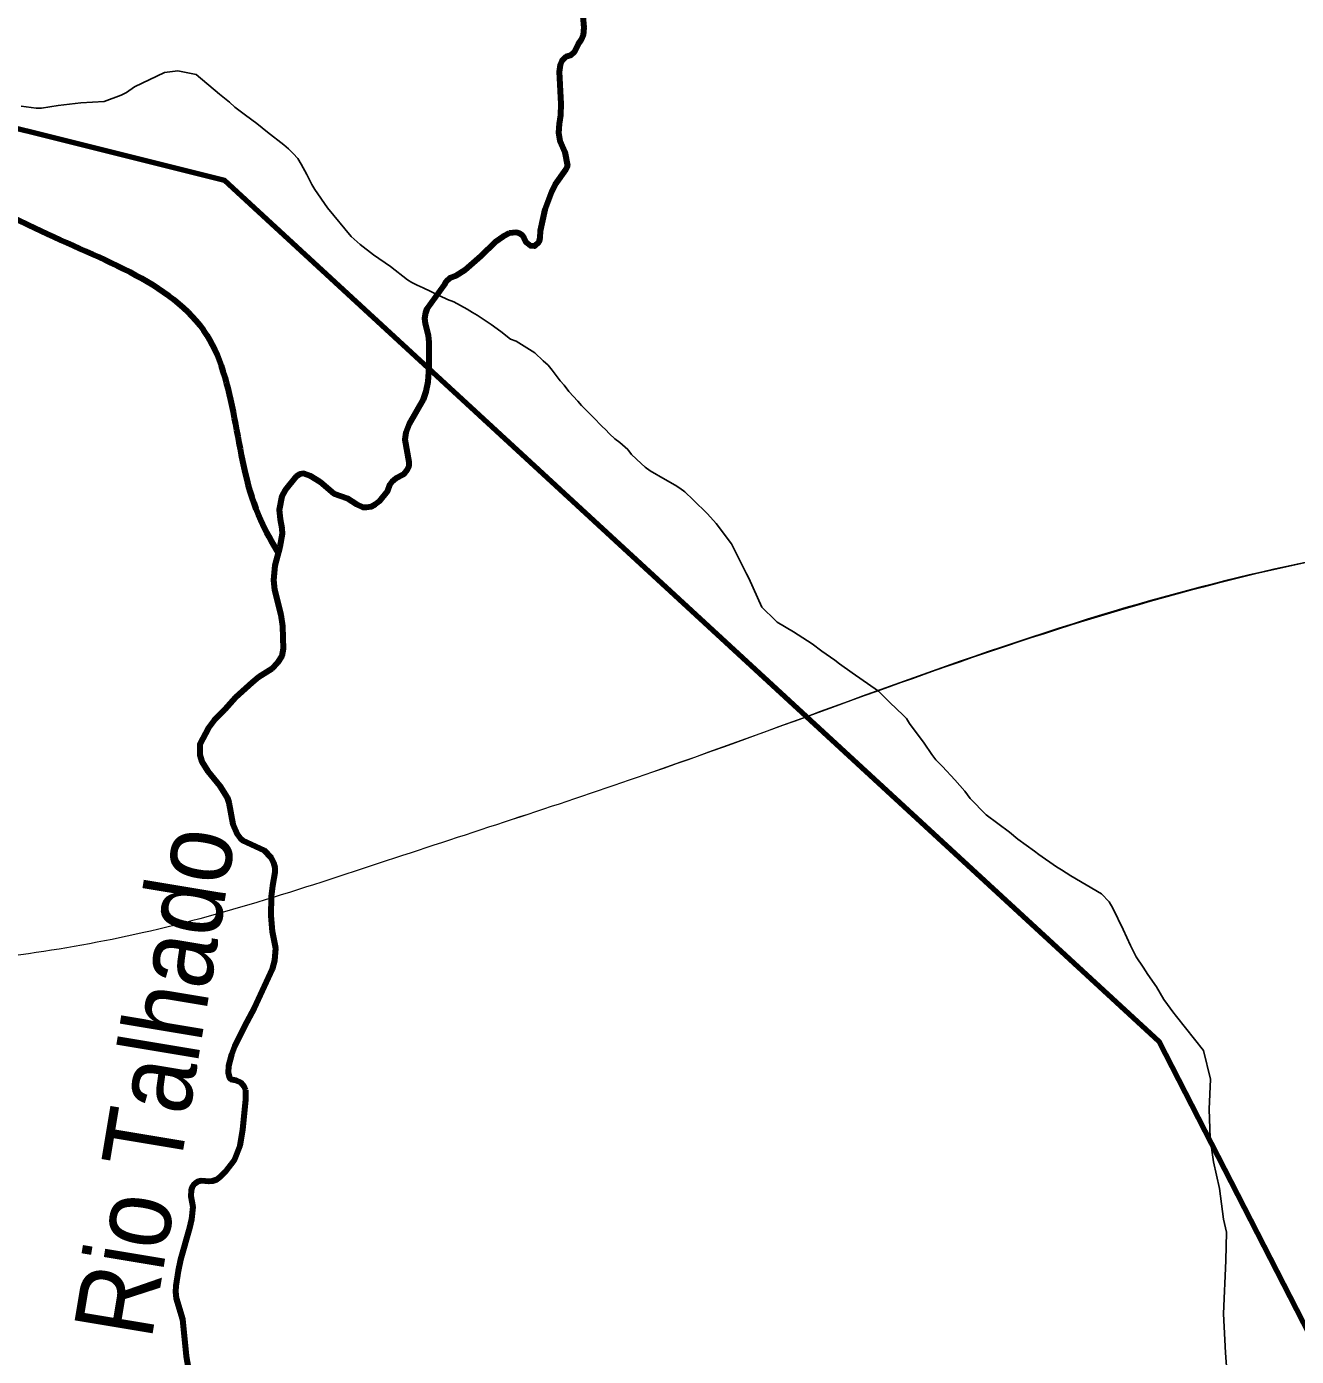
# Model space of a CAD drawing. Extents: x 553962 to 842807, y 8883888 to 9032388.
# Drawn here: x 619995 to 628026, y 8951515 to 8959925 of the extents above; entities that cross this region are included whole.
import ezdxf
from ezdxf.enums import TextEntityAlignment as Align

# ---------------------------------------------------------------- set-up
doc = ezdxf.new("R2010")
doc.units = 0
doc.header["$LTSCALE"] = 200
for name, color, linetype, lineweight in [('12', 7, 'Continuous', 25), ('24', 7, 'Continuous', 25), ('28', 7, 'Continuous', 40), ('57', 7, 'Continuous', 13), ('9', 7, 'Continuous', 90)]:
    doc.layers.add(name, color=color, linetype=linetype, lineweight=lineweight)
doc.layers.add('49', color=7, linetype='Continuous')

msp = doc.modelspace()

# ---------------------------------------------------------------- linework, layer by layer
at = {"layer": '12'}
for points in [[(619960.1, 8959421.4), (620056, 8959410.5), (620088, 8959410.6), (620193.3, 8959426.8), (620302, 8959438.9), (620338.3, 8959444), (620485.1, 8959452.2), (620592.3, 8959491.5), (620626.6, 8959508.6), (620677.1, 8959543.7), (620866.8, 8959636.1), (620950.1, 8959645.3), (621067.6, 8959622.4), (621213.8, 8959498.5), (621277.5, 8959446.5), (621310.7, 8959416.5), (621378.9, 8959364.5), (621451.2, 8959312.6), (621517.4, 8959257.6), (621620.6, 8959177.6), (621652, 8959151.6), (621681.1, 8959122.6), (621709.4, 8959090.6), (621730.8, 8959055.6), (621766, 8958989.6), (621797.6, 8958926.5), (621816.7, 8958894.5), (621897.9, 8958779.4), (622047.1, 8958598.4), (622104.4, 8958547.4), (622189, 8958482.4), (622295.2, 8958408.5), (622402.8, 8958323.5), (622432, 8958306.5), (622464.2, 8958290.6), (622503.3, 8958272.6), (622656.9, 8958198.7), (622695.9, 8958184.8), (622781.7, 8958137.8), (622814.5, 8958116.8), (622845, 8958100.9), (622933, 8958040.9), (622994, 8957997), (623055.6, 8957949), (623090.1, 8957935), (623208.6, 8957861.1), (623261.3, 8957811.1), (623293.1, 8957783.1), (623319, 8957753.1), (623370.1, 8957684.1), (623394.1, 8957657.1), (623423, 8957618), (623480.8, 8957556), (623503.5, 8957528), (623577.3, 8957455), (623634.3, 8957397), (623656.2, 8957377), (623681.5, 8957349), (623715.2, 8957318), (623746.4, 8957294), (623796.4, 8957250.1), (623820, 8957220), (623881.1, 8957162.1), (623907.7, 8957139.1), (623938.3, 8957116.1), (624032.6, 8957060.1), (624097.3, 8957025.2), (624126.4, 8957005.2), (624156.6, 8956982.2), (624209.6, 8956933.2), (624300.1, 8956843.2), (624356.6, 8956783.2), (624452.3, 8956653.2), (624547.5, 8956464), (624563.3, 8956437), (624643.8, 8956253.8), (624732.1, 8956169.8), (624741.4, 8956157.8), (624844.8, 8956096.9), (624963, 8956021), (625024.6, 8955976), (625106.9, 8955919.1), (625134.8, 8955896.1), (625215.8, 8955838.1), (625381.6, 8955722.2), (625453.3, 8955650.2), (625539.4, 8955570.2), (625559, 8955549.2), (625578.1, 8955517.2), (625672.3, 8955394.1), (625719.6, 8955321.1), (625744.1, 8955288.1), (625787.2, 8955246.1), (625865, 8955162.1), (625928.3, 8955090.1), (625962.8, 8955044), (626062.5, 8954941)], [(626062.5, 8954941), (626210.1, 8954830.1), (626263.6, 8954786.1), (626369.3, 8954710.2), (626395.7, 8954688.2), (626508.6, 8954610.2), (626539.2, 8954592.2), (626598.2, 8954554.3), (626792.1, 8954439.4), (626840.8, 8954390.4), (626864.8, 8954350.4), (626929.5, 8954214.3), (626976, 8954113.2), (627012.7, 8954042.1), (627056.3, 8953977.1), (627085.1, 8953931.1), (627140.4, 8953852), (627187.4, 8953773), (627209.8, 8953740), (627243.8, 8953694), (627268.1, 8953665), (627437.5, 8953449.9)], [(627437.5, 8953449.9), (627481.8, 8953267.7), (627474.2, 8953079.4), (627481, 8952894.1), (627502, 8952745.9), (627539.5, 8952577.7), (627565.1, 8952382.4), (627583.5, 8952301.3), (627578.9, 8952122), (627564.2, 8951783.5), (627578, 8951538.1), (627594.5, 8951309.8), (627615.6, 8951152.6), (627641.3, 8950944.3), (627690, 8950694), (627726.6, 8950540.8), (627780.8, 8950380.6), (627876.2, 8950172.5), (627886.3, 8950067.3), (627860.6, 8949911), (627825.7, 8949779.8), (627813.3, 8949686.6)]]:
    msp.add_lwpolyline(points, dxfattribs=at)
at = {"layer": '24'}
for points in [[(623511.8, 8959991.9), (623518.8, 8959918.8), (623515.2, 8959871.7), (623503, 8959841.6), (623483.8, 8959814.6), (623458.3, 8959764.4), (623435.3, 8959743.4), (623405.8, 8959733.3), (623380.1, 8959708.2), (623370, 8959684.2), (623363, 8959639.1), (623374, 8959437.8), (623371.3, 8959365.7), (623362.7, 8959309.6), (623359.5, 8959254.5), (623367, 8959203.4), (623399.7, 8959131.4), (623414.8, 8959045.2), (623404.2, 8959022.2), (623338.3, 8958926.9), (623315, 8958880.8), (623272.9, 8958769.6), (623243.1, 8958633.3), (623241.6, 8958590.3), (623234, 8958561.2), (623207.1, 8958537.1), (623180.9, 8958538.1), (623154, 8958559.1), (623142.4, 8958588.1), (623129.2, 8958606.1), (623114.3, 8958616.1), (623091.3, 8958624.1), (623048.1, 8958618)], [(623048.1, 8958618), (623008.6, 8958598.9), (622961, 8958563.8), (622867, 8958474.5), (622765.3, 8958385.2), (622710.3, 8958350.1), (622672.6, 8958336), (622645.8, 8958310.9), (622635.8, 8958292.8), (622526.4, 8958139.4), (622516.5, 8958114.4), (622511.7, 8958078.3), (622515.3, 8958048.3), (622533.3, 8957971.2), (622537.7, 8957930.1), (622539.2, 8957771.9), (622532.6, 8957678.7), (622519.6, 8957617.6), (622503, 8957566.5), (622414.7, 8957413.1), (622392.8, 8957358), (622387.2, 8957313.9), (622413.1, 8957173.7), (622412, 8957144.7), (622401.3, 8957121.6), (622379.3, 8957091.6), (622329.5, 8957067.4), (622303.6, 8957046.4), (622292.3, 8957028.3), (622277.2, 8956988.2), (622224.7, 8956922.1), (622199.4, 8956902), (622173.6, 8956888.9), (622144.5, 8956882.9), (622124.1, 8956884.8), (622082.2, 8956903.8), (622023.4, 8956940.8)], [(622023.4, 8956940.8), (621940, 8956970.7), (621852.9, 8957044.7), (621852.9, 8957044.7), (621788.3, 8957084.6), (621747.1, 8957098.6), (621722, 8957094.5), (621699.9, 8957079.5), (621630.5, 8956993.2), (621609.1, 8956955.1), (621593, 8956869), (621597.7, 8956809.9), (621609.5, 8956752.8), (621610.3, 8956716.8), (621596.7, 8956635.6), (621564.2, 8956517.4), (621555.7, 8956425.2), (621563.4, 8956363.1), (621602.1, 8956205), (621612.3, 8956132.8), (621617.2, 8955989.6), (621609.4, 8955942.6), (621581.9, 8955900.4), (621546.5, 8955864.3), (621462.3, 8955810.1), (621421.6, 8955778), (621315.5, 8955681.7), (621248.5, 8955606.5), (621180.3, 8955539.2), (621144.2, 8955490.1), (621090.8, 8955387.9), (621089.6, 8955318.8), (621102.6, 8955276.7), (621141.2, 8955216.7), (621216.2, 8955123.7), (621263.9, 8955050.6), (621273.7, 8955018.6), (621298.4, 8954880.4), (621326.6, 8954818.3), (621344.8, 8954792.3), (621361.2, 8954778.3), (621494.9, 8954716.5), (621540.7, 8954668.5), (621556.5, 8954637.4), (621563.9, 8954607.4), (621564.5, 8954574.3), (621548.8, 8954491.2), (621540.9, 8954424.1), (621539.7, 8954301.9), (621548, 8954202.7), (621568.6, 8954096.6), (621562.7, 8954019.5), (621547, 8953964.4), (621433.8, 8953717.8), (621371.7, 8953602.5), (621309.6, 8953474.2), (621290.3, 8953424.1), (621271.3, 8953352), (621268.5, 8953307.9), (621278.3, 8953276.9), (621286.8, 8953268.9), (621318.5, 8953261.9), (621350.1, 8953247.9), (621369.2, 8953222.9), (621379.6, 8953197.9)], [(621379.6, 8953197.9), (621378.8, 8953137.8), (621359.7, 8952949.5), (621342.4, 8952846.3), (621307.8, 8952755.1), (621249.5, 8952681.9), (621219.1, 8952650.8), (621195, 8952631.7), (621171.1, 8952622.7), (621146.2, 8952620.6), (621100.1, 8952625.6), (621079.8, 8952621.5), (621057, 8952606.5), (621039.6, 8952581.4), (621035.3, 8952565.4), (621033.6, 8952527.3), (621045.1, 8952461.2), (621037.1, 8952383.1), (621025.7, 8952328), (620968.5, 8952127.6), (620952.3, 8952055.4), (620937.5, 8951961.3), (620936.1, 8951922.2), (620941.1, 8951883.2), (620980.3, 8951750), (621003, 8951516.7), (621017.4, 8951444.6)]]:
    msp.add_lwpolyline(points, dxfattribs=at)
at = {"layer": '28', "lineweight": 80}
msp.add_lwpolyline([(610031.8, 8962217.2), (616214.5, 8960212.5), (621246, 8958953.8), (627155.1, 8953509.2), (629934.5, 8948091.8)], dxfattribs=at)
at = {"layer": '57'}
for points in [[(646003, 8949251.6), (644721.9, 8950215.5), (643492.6, 8951234.6), (642099.6, 8952556.8), (640992.4, 8953664.6), (640171, 8954236.3), (637456.5, 8955772.9), (636135, 8956237.5), (634599.2, 8956630.6), (632599.1, 8956773.5), (629063.1, 8956702), (626348.7, 8956058.8), (623953.8, 8955209.7), (622371.6, 8954682.1), (620725.9, 8954192.9), (619183.7, 8953970.3), (617209.7, 8953965.7), (615658.4, 8954379), (614681.6, 8955057.1), (613704.6, 8955684.2), (612906.2, 8956374.2), (612068.3, 8956835.4), (609416.9, 8956401.3), (608625.2, 8956035.7), (607870.9, 8955517.4), (607396.1, 8954883.6), (607164, 8954388.6), (606950.6, 8954069.9)], [(646003, 8949251.6), (644721.9, 8950215.5), (643521.3, 8951208.7), (642428.2, 8952239.5), (641741.8, 8952914.9), (640407.4, 8954089.3), (638333.9, 8955336.1), (636237.3, 8956206.4), (633646.8, 8956732.8), (631365, 8956802.2), (629312, 8956729.1), (626793.2, 8956204.6), (623953.8, 8955209.7), (622371.6, 8954682.1), (620725.9, 8954192.9), (619183.7, 8953970.3), (617209.7, 8953965.7), (615658.4, 8954379), (614681.6, 8955057.1), (613704.6, 8955684.2), (612906.2, 8956374.2), (612068.3, 8956835.4), (609416.9, 8956401.3), (608625.2, 8956035.7), (607870.9, 8955517.4), (607396.1, 8954883.6), (607164, 8954388.6), (606950.6, 8954069.9)]]:
    msp.add_spline(points, degree=3, dxfattribs=at)
at = {"layer": '9'}
for points in [[(623511.8, 8959991.9), (623518.8, 8959918.8), (623515.2, 8959871.7), (623503, 8959841.6), (623483.8, 8959814.6), (623458.3, 8959764.4), (623435.3, 8959743.4), (623405.8, 8959733.3), (623380.1, 8959708.2), (623370, 8959684.2), (623363, 8959639.1), (623374, 8959437.8), (623371.3, 8959365.7), (623362.7, 8959309.6), (623359.5, 8959254.5), (623367, 8959203.4), (623399.7, 8959131.4), (623414.8, 8959045.2), (623404.2, 8959022.2), (623338.3, 8958926.9), (623315, 8958880.8), (623272.9, 8958769.6), (623243.1, 8958633.3), (623241.6, 8958590.3), (623234, 8958561.2), (623207.1, 8958537.1), (623180.9, 8958538.1), (623154, 8958559.1), (623142.4, 8958588.1), (623129.2, 8958606.1), (623114.3, 8958616.1), (623091.3, 8958624.1), (623048.1, 8958618)], [(623048.1, 8958618), (623008.6, 8958598.9), (622961, 8958563.8), (622867, 8958474.5), (622765.3, 8958385.2), (622710.3, 8958350.1), (622672.6, 8958336), (622645.8, 8958310.9), (622635.8, 8958292.8), (622526.4, 8958139.4), (622516.5, 8958114.4), (622511.7, 8958078.3), (622515.3, 8958048.3), (622533.3, 8957971.2), (622537.7, 8957930.1), (622539.2, 8957771.9), (622532.6, 8957678.7), (622519.6, 8957617.6), (622503, 8957566.5), (622414.7, 8957413.1), (622392.8, 8957358), (622387.2, 8957313.9), (622413.1, 8957173.7), (622412, 8957144.7), (622401.3, 8957121.6), (622379.3, 8957091.6), (622329.5, 8957067.4), (622303.6, 8957046.4), (622292.3, 8957028.3), (622277.2, 8956988.2), (622224.7, 8956922.1), (622199.4, 8956902), (622173.6, 8956888.9), (622144.5, 8956882.9), (622124.1, 8956884.8), (622082.2, 8956903.8), (622023.4, 8956940.8)], [(622023.4, 8956940.8), (621940, 8956970.7), (621852.9, 8957044.7), (621852.9, 8957044.7), (621788.3, 8957084.6), (621747.1, 8957098.6), (621722, 8957094.5), (621699.9, 8957079.5), (621630.5, 8956993.2), (621609.1, 8956955.1), (621593, 8956869), (621597.7, 8956809.9), (621609.5, 8956752.8), (621610.3, 8956716.8), (621596.7, 8956635.6), (621564.2, 8956517.4), (621555.7, 8956425.2), (621563.4, 8956363.1), (621602.1, 8956205), (621612.3, 8956132.8), (621617.2, 8955989.6), (621609.4, 8955942.6), (621581.9, 8955900.4), (621546.5, 8955864.3), (621462.3, 8955810.1), (621421.6, 8955778), (621315.5, 8955681.7), (621248.5, 8955606.5), (621180.3, 8955539.2), (621144.2, 8955490.1), (621090.8, 8955387.9), (621089.6, 8955318.8), (621102.6, 8955276.7), (621141.2, 8955216.7), (621216.2, 8955123.7), (621263.9, 8955050.6), (621273.7, 8955018.6), (621298.4, 8954880.4), (621326.6, 8954818.3), (621344.8, 8954792.3), (621361.2, 8954778.3), (621494.9, 8954716.5), (621540.7, 8954668.5), (621556.5, 8954637.4), (621563.9, 8954607.4), (621564.5, 8954574.3), (621548.8, 8954491.2), (621540.9, 8954424.1), (621539.7, 8954301.9), (621548, 8954202.7), (621568.6, 8954096.6), (621562.7, 8954019.5), (621547, 8953964.4), (621433.8, 8953717.8), (621371.7, 8953602.5), (621309.6, 8953474.2), (621290.3, 8953424.1), (621271.3, 8953352), (621268.5, 8953307.9), (621278.3, 8953276.9), (621286.8, 8953268.9), (621318.5, 8953261.9), (621350.1, 8953247.9), (621369.2, 8953222.9), (621379.6, 8953197.9)], [(621379.6, 8953197.9), (621378.8, 8953137.8), (621359.7, 8952949.5), (621342.4, 8952846.3), (621307.8, 8952755.1), (621249.5, 8952681.9), (621219.1, 8952650.8), (621195, 8952631.7), (621171.1, 8952622.7), (621146.2, 8952620.6), (621100.1, 8952625.6), (621079.8, 8952621.5), (621057, 8952606.5), (621039.6, 8952581.4), (621035.3, 8952565.4), (621033.6, 8952527.3), (621045.1, 8952461.2), (621037.1, 8952383.1), (621025.7, 8952328), (620968.5, 8952127.6), (620952.3, 8952055.4), (620937.5, 8951961.3), (620936.1, 8951922.2), (620941.1, 8951883.2), (620980.3, 8951750), (621003, 8951516.7), (621017.4, 8951444.6)]]:
    msp.add_lwpolyline(points, dxfattribs=at)
msp.add_spline([(592698.5, 8977198.4), (599903.5, 8973292.7), (608459.2, 8968138.2), (612674.8, 8965332.6), (616842, 8962096.4), (620005, 8958671.2), (621134, 8957974.7), (621473.4, 8956805.3), (621586.2, 8956597.5)], degree=3, dxfattribs=at)

# ---------------------------------------------------------------- texts
at = {"layer": '49', "width": 0.9}
msp.add_text('Rio Talhado', height=500, rotation=80.538, dxfattribs=at).set_placement((621050.4, 8953212.3), align=Align.CENTER)

doc.saveas('drawing.dxf')
